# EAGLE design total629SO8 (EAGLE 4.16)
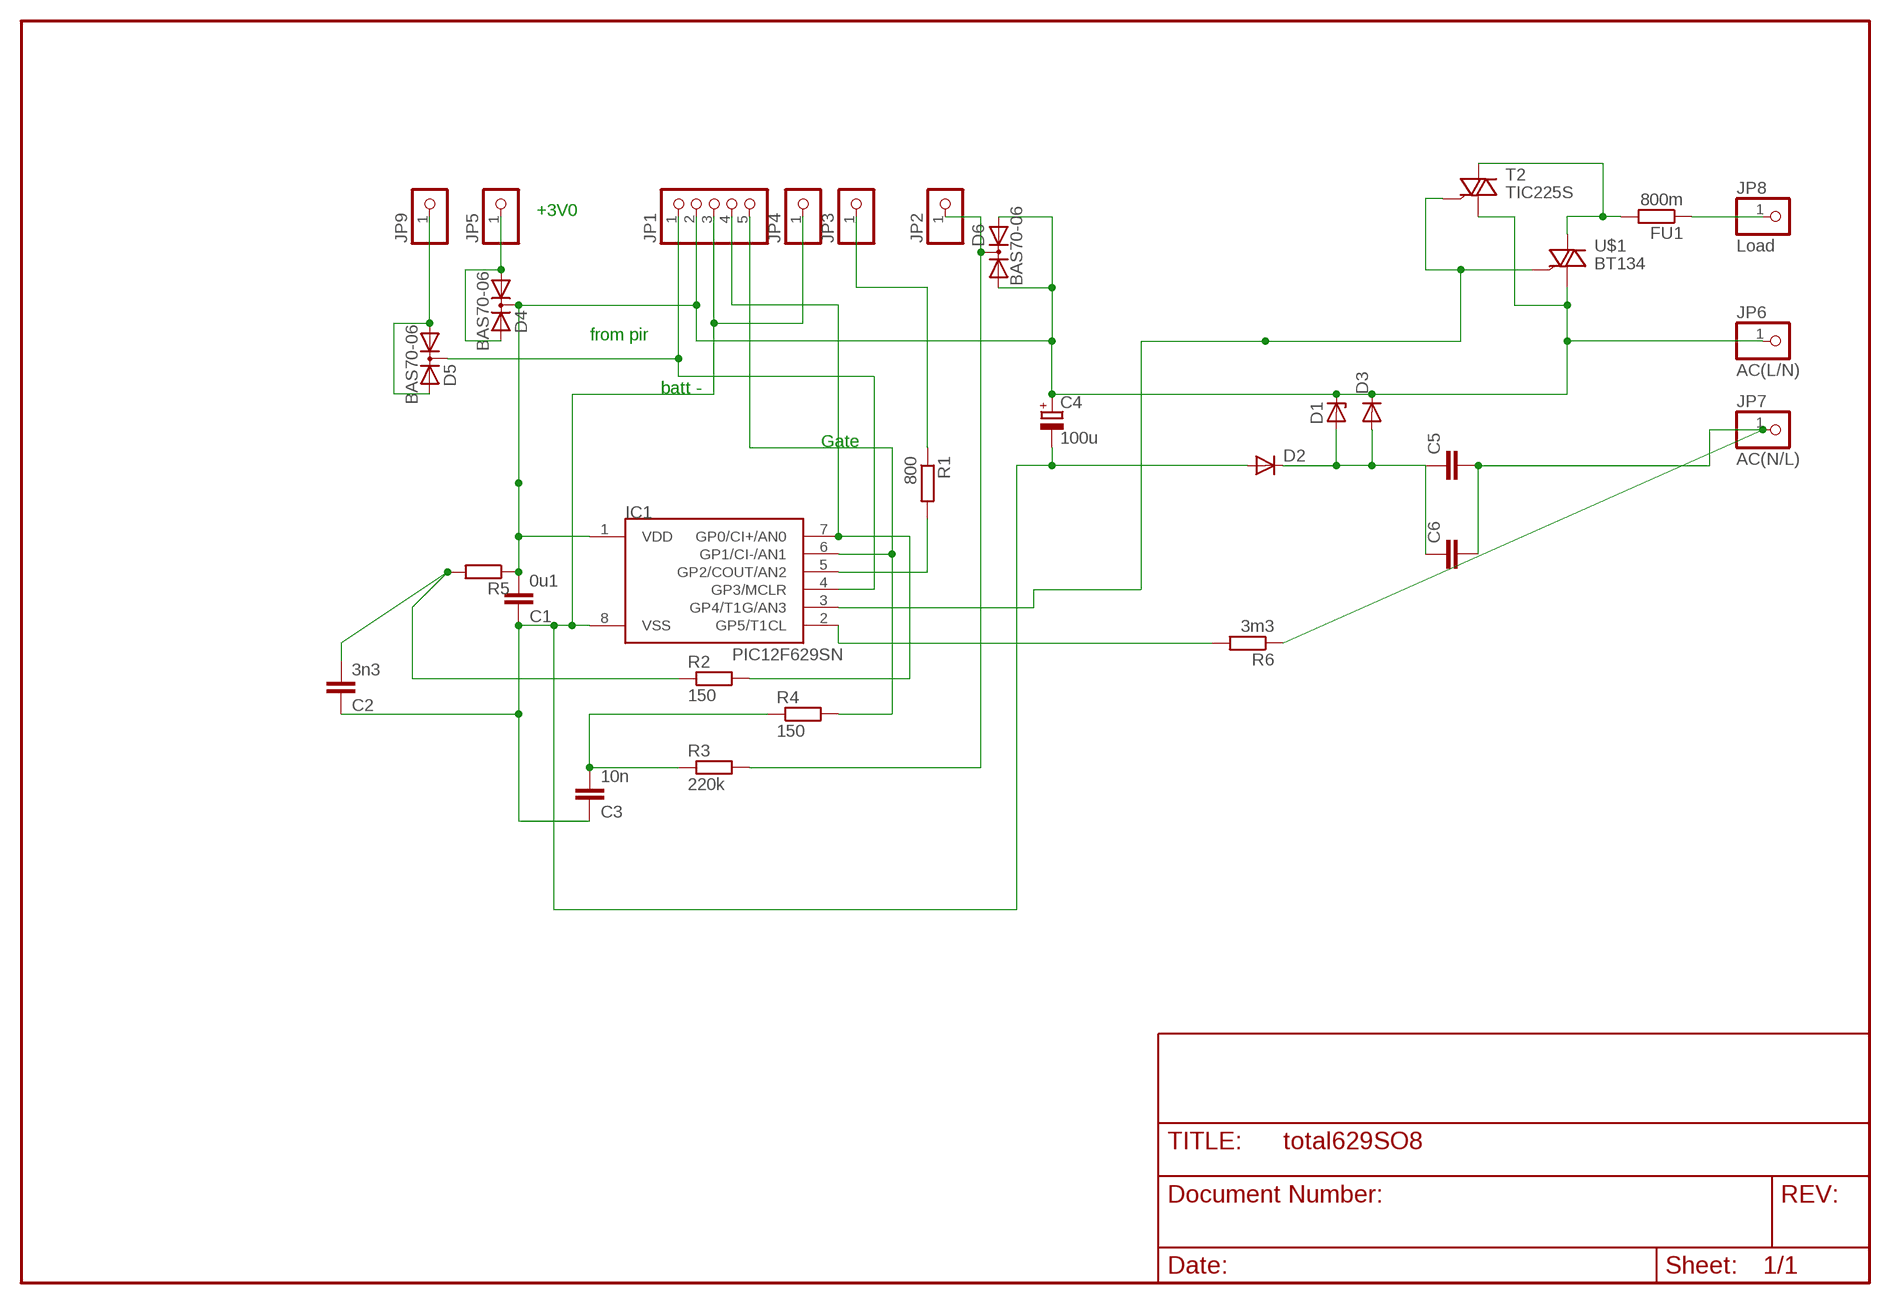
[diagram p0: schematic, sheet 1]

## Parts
C1  0u1  C-EUC1206  [C1206]
C2  3n3  C-EUC1206  [C1206]
C3  10n  C-EUC1206  [C1206]
C4  100u  CPOL-EUE2,5-6E  [E2,5-6E]
C5  C-EU075-032X103  [C075-032X103]
C6  C-EU102-043X133  [C102-043X133]
D1  ZENER-DIODEDO35Z10  [DO35Z10]
D2  DIODE-MELF-MLL41  [MELF-MLL41]
D3  DIODE-MINIMELF  [MINIMELF]
D4  BAS70-06  [SOT23]
D5  BAS70-06  [SOT23]
D6  BAS70-06  [SOT23]
FU1  800m  R-EU_0204/7  [0204/7]
IC1  PIC12F629SN  [SO-08]
JP1  PINHD-1X5  [1X05]
JP2  PINHD-1X1  [1X01]
JP3  PINHD-1X1  [1X01]
JP4  PINHD-1X1  [1X01]
JP5  PINHD-1X1  [1X01]
JP6  AC(L/N)  PINHD-1X1  [1X01]
JP7  AC(N/L)  PINHD-1X1  [1X01]
JP8  Load  PINHD-1X1  [1X01]
JP9  PINHD-1X1  [1X01]
R1  800  R-EU_M1206  [M1206]
R2  150  R-EU_M1206  [M1206]
R3  220k  R-EU_M1206  [M1206]
R4  150  R-EU_M1206  [M1206]
R5  R-EU_0613/5V  [P0613V]
R6  3m3  R-EU_R1206  [R1206]
T2  TIC225S  [TO220DS]
U$1  BT134  [SOT223]

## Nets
GATE: JP3.1 R1.1
N$1: IC1.5(GP2/COUT/AN2) R1.2
N$2: FU1.1 JP8.1
N$4: IC1.7(GP0/CI+/AN0) JP1.4 R2.2
N$6: C2.2 R2.1 R5.2
N$7: C3.2 R3.1 R4.1
N$8: IC1.6(GP1/CI-/AN1) JP1.5 R4.2
N$9: FU1.2 T2.A2 U$1.P$2(A2)
N$10: IC1.3(GP4/T1G/AN3) T2.G U$1.P$3(G)
N$12: C5.1 C6.1 D1.A D2.C D3.A
N$14: IC1.2(GP5/T1CL) R6.2
N$37: C5.2 C6.2 JP7.1 R6.1
PIR: D5.3(C) IC1.4(GP3/MCLR) JP1.1
SENSOR: D5.1(A1) D5.2(A2) JP9.1
V3: C1.2 C4.+ D1.C D3.C D4.3(C) D6.1(A1) D6.2(A2) IC1.1(VDD) JP1.2 JP6.1 R5.1 T2.A1 U$1.P$1(A1)
V+3: D6.3(C) JP2.1 R3.2
V+BATT: D4.1(A1) D4.2(A2) JP5.1
V-: C1.1 C2.1 C3.1 C4.- D2.A IC1.8(VSS) JP1.3 JP4.1

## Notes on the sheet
- +3V0
- from pir
- batt -
- Gate

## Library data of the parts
C1-C3 C5 = rcl:C-EU: CAPACITOR, European symbol
C4 = rcl(2):CPOL-EU: POLARIZED CAPACITOR, European symbol
C6 = rcl-2:C-EU: CAPACITOR, European symbol
D1 = diode-1:ZENER-DIODE: Z-Diode
D2 D3 = diode-1:DIODE-: DIODE
D4-D6 = diode-1:BAS70-06: Silicon Schottky Diodes General-purpose diode for high-speed switching
FU1 R1-R6 = rcl:R-EU_: RESISTOR, European symbol
IC1 = microchip-3:PIC12F6*: uPC nW 1k Program Flash memory 2x Timer Comparator 10b A/D converter/ 4xIN
JP1 = pinhead:PINHD-1X5: PIN HEADER
JP2-JP9 = pinhead:PINHD-1X1: PIN HEADER
T2 = triac:TIC225S: TRIAC
U$1 = triggered_devices:BT134

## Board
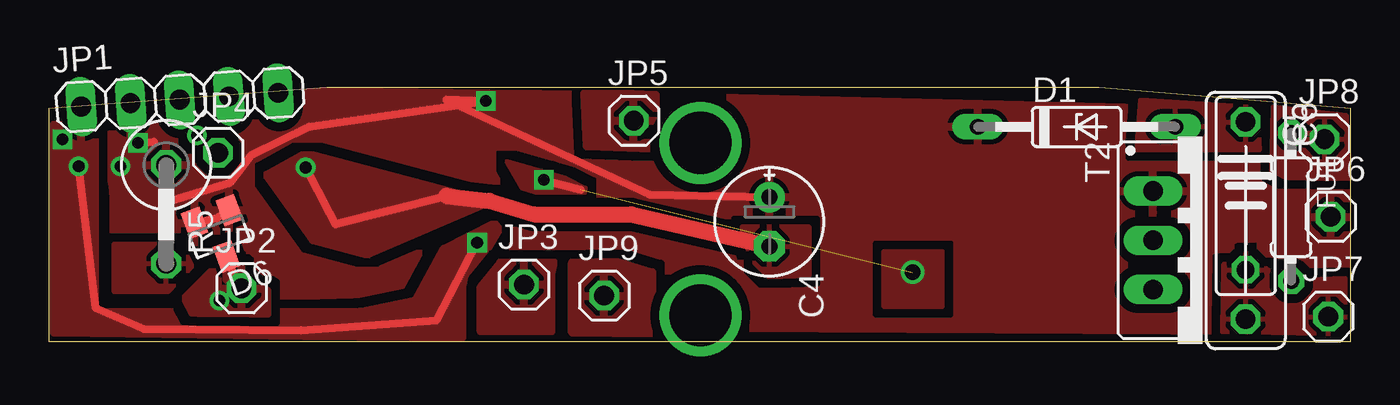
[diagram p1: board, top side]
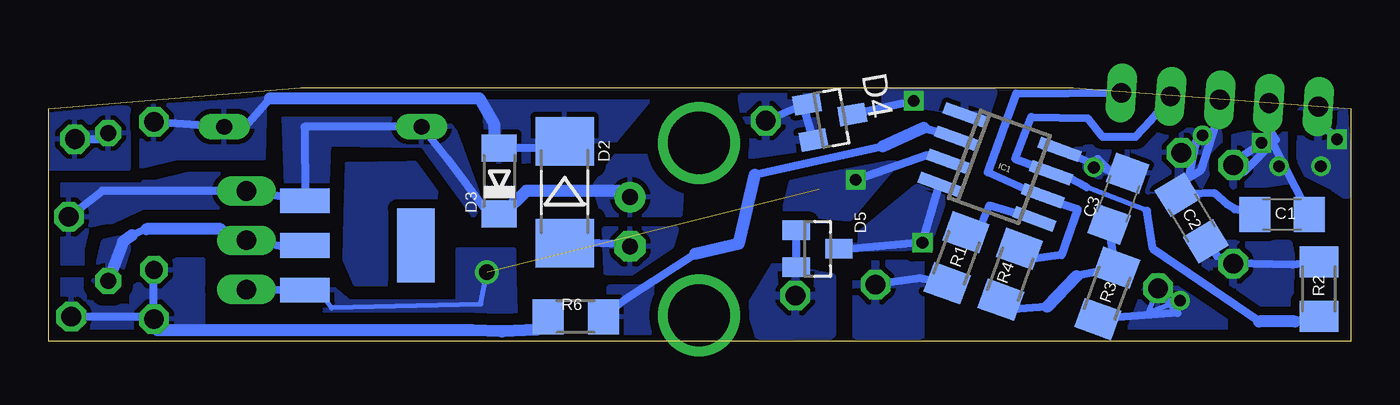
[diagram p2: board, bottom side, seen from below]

Size 67.04 x 13.08 mm. Coordinates in mm from the lower left corner, seen from the top.
Outline: 0,0 67.04,0 67.04,11.86 67.02,11.99 54.06,13.08 18,13.07 14.31,13.08 0,11.99 0,0
Copper layers (1*16): Top 0.035mm / dielectric 1.5mm / Bottom 0.035mm
Design rules "default": minimum track width 10mil, minimum drill 24mil, track to track 18mil, track to pad 18mil, pad to pad 8mil, via to via 8mil, smd to smd 8mil, copper to edge 1mil, drill to drill 8mil, minimum pad ring 10mil, minimum via ring 8mil, stop-mask expansion 4mil, vias tented up to drill 0mil, thermal gap 10mil

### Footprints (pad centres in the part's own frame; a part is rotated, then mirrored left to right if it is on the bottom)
C1206 = smd 1.6 x 1.8: 1 -1.4,0; 2 1.4,0
E2,5-6E = drill 0.813 pad 1.575 round: + -1.27,0 | drill 0.813 pad 1.575 octagon: - 1.27,0
C075-032X103 = drill 0.914 octagon: 1 -3.81,0; 2 3.81,0
C102-043X133 = drill 1.016 octagon: 1 -5.08,0; 2 5.08,0
DO35Z10 = drill 0.813 long: A 5.08,0; C -5.08,0
MELF-MLL41 = smd 2.5 x 3: A 2.625,0; C -2.625,0
MINIMELF = smd 1.4 x 1.8: A 1.7,0; C -1.7,0
SOT23 = smd 1 x 1.4: 1 -0.95,-1.1; 2 0.95,-1.1; 3 0,1.1
0204/7 = drill 0.813 octagon: 1 -3.81,0; 2 3.81,0
SO-08 = smd 0.6 x 2.2: 1 -1.905,-2.6; 2 -0.635,-2.6; 3 0.635,-2.6; 4 1.905,-2.6; 5 1.905,2.6; 6 0.635,2.6; 7 -0.635,2.6; 8 -1.905,2.6
1X05 = drill 1.016 long: 1 -5.08,0; 2 -2.54,0; 3 0,0; 4 2.54,0; 5 5.08,0
1X01 = drill 1.016 octagon: 1 0,0
M1206 = smd 1.6 x 2: 1 -1.4,0; 2 1.4,0
P0613V = drill 1.016 octagon: 1 -2.54,0; 2 2.54,0
R1206 = smd 1.6 x 1.803: 1 -1.422,0; 2 1.422,0
TO220DS = drill 1.016 long: A1 -2.54,-2.54; A2 0,-2.54; G 2.54,-2.54
SOT223 = smd 1.27 x 2.54: P$1 0.7,1.3; P$2 3,1.3; P$3 5.3,1.3 | smd 3.81 x 1.93: P$4 3,7

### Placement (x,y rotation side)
C1  3.55,6.53 0 bottom
C2  8.2,6.35 301.3 bottom
C3  11.98,7.34 250 bottom
C4  37.11,6.15 270 top
C5  61.62,7.49 270 top
C6  61.62,6.22 270 top
D1  52.92,11.04 0 top
D2  40.48,7.68 270 bottom
D3  43.84,8.25 90 bottom
D4  26.75,11.49 280 bottom
D5  27.46,4.76 270 bottom
D6  8.79,5.39 200 top
FU1  63.97,6.92 270 top
IC1  18.09,8.98 250 bottom
JP1  6.75,12.44 4 top
JP2  9.93,2.73 0 top
JP3  24.47,2.92 0 top
JP4  8.72,9.71 0 top
JP5  30.12,11.36 0 top
JP6  66,6.41 0 top
JP7  65.88,1.27 0 top
JP8  65.68,10.41 0 top
JP9  28.6,2.34 0 top
R1  20.31,4.3 70 bottom
R2  1.64,2.69 270 bottom
R3  12.55,2.46 250 bottom
R4  17.54,3.45 70 bottom
R5  6.06,6.54 270 top
R6  39.9,1.27 0 bottom
T2  59.4,5.2 270 top
U$1  55.14,7.93 270 bottom

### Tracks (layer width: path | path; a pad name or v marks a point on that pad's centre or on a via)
GATE
  Bottom 0.406: R1.1 22.2,3.24 JP3.1
  pour Bottom (rank 2): 22.31,4.38 25.49,4.38 25.49,0.31 22.12,0.31 22.12,4.19
  pour Top: 23.27,4.06 26,4.06 25.87,3.49 25.87,0.5 22.25,0.5 22.25,2.79
N$1
  Bottom 0.406: IC1.5 18.63,6.98 19.33,5.33 R1.2
N$2
  Bottom 0.406: FU1.1 64.03,10.73 64.35,10.41 JP8.1
  pour Top: 63.02,12.06 62.95,8.82 63.65,8.44 66.89,8.38 66.83,11.62
  pour Bottom: 62.95,12 62.95,8.88 67.02,8.88 67.02,11.68 63.34,12.06
N$4
  Bottom 0.254: 10.5,6.73 13.61,7.93
  Bottom 0.406: JP1.4 9.42,12.38 10.31,11.36 11.07,10.54 12.79,10.54 13.55,11.49 16.47,11.55 17.3,9.39 IC1.7 15.33,8.63 14.44,8.38 13.61,7.93 | 10.5,6.73 10.19,4.76 4.72,1.01 | R2.2 2.88,1.01
  Bottom 0.61: 2.88,1.01 4.72,1.01
N$6
  Bottom 0.406: R2.1 3.01,3.93 R5.2 6.88,4.38 C2.2
  pour Bottom: 3.2,5.01 7.14,5.01 8.15,4.25 4.79,1.96 3.14,1.96 3.07,4.38
  pour Top (isolate 0.61): 6.82,5.01 7.39,3.87 6.12,2.54 3.39,2.54 3.39,5.01
N$7
  Bottom 0.406: C3.2 12.15,3.87 R3.1 14.12,3.36 | R4.1 17.42,1.65 15.65,1.77
  Bottom 0.61: 14.12,3.36 15.65,1.77
N$8
  Bottom 0.406: JP1.5 17.23,12.76 18.69,8.69 16.47,7.68 15.96,7.42 | 15.96,7.42 IC1.6 | 15.96,7.42 14.06,6.79 14.88,4.44 16.73,4.19 R4.2
N$9
  Bottom 0.406: U$1.P$2 54.25,4.76 T2.A2 56.98,5.14 58.19,5.77 | 62,5.77 62.76,5.46
  Bottom 0.61: FU1.2 63.21,5.14 62.76,5.46 | 58.19,5.77 62,5.77
  pour Bottom: 63.4,5.33 64.22,5.14 64.73,3.11 63.59,2.6 62.89,4.82
N$10  (via drill 0.6, 0.8)  (1 unrouted)
  Top 0.406: v25.49,8.31 27.39,7.81
  Bottom 0.254: v44.48,3.55 44.79,1.9 52.48,1.71 53.18,2.66 53.68,2.66 U$1.P$3
  Bottom 0.406: IC1.3 21.81,9.58 v25.49,8.31 | T2.G 56.98,2.6 U$1.P$3
  pour Bottom: 23.52,9.14 25.87,6.34 29.11,6.66 28.73,8.19 23.77,9.14
  pour Bottom (isolate 0.61): 43.08,4.69 46,4.69 46,2.03 51.59,2.03 52.79,3.04 52.79,1.39 43.02,1.46 43.08,4.12
  pour Top: 43.02,4.63 46,4.63 46,1.77 43.02,1.77
  pour Top (isolate 0.61): 27.65,7.87 26.63,8.38 23.58,9.27 24.54,7.62 27.58,7.62
N$11  (via drill 3.2)
  other vias: 33.55,10.22
N$12
  Bottom 0.406: 55.65,12.5 56.92,11.04 D1.A 58.19,11.04 C6.1 | 44.09,10.15 43.89,9.95 D3.A 40.81,9.95 40.48,10.28 D2.C
  Bottom 0.61: 55.65,12.5 44.86,12.5 44.09,11.17 44.09,10.15
  pour Bottom: 57.05,12.38 62.26,12.06 62.26,9.01 60.41,9.46 55.97,9.46 55.91,12.5
  pour Top: 56.22,12.44 62.19,12.06 62.32,9.84 56.03,9.84
  pour Bottom (isolate 0.61, rank 3): 36.16,12.63 44.67,12.82 44.41,9.27 38.7,9.33 36.22,12.31
N$13  (via drill 3.2)
  other vias: 33.55,1.33
N$14
  Bottom 0.406: IC1.2 22,10.98 | 24.09,10.03 30.7,8.57 | R6.2 37.43,2.09 33.74,4.5
  Bottom 0.61: 22,10.98 24.09,10.03 | 30.7,8.57 31.52,5.01 33.74,4.5
  pour Bottom (isolate 0.305, rank 3): 35.97,3.11 36.09,0.38 38.19,0.38 38.19,2.79 36.66,3.11
N$37
  Bottom 0.406: JP7.1 61.56,1.27 61.62,1.2 C6.2 C5.2 | R6.1 41.9,0.59
  Bottom 0.61: C6.2 61.43,0.57 45.24,0.57 43.71,0.5 41.9,0.59
  pour Top: 60.48,3.93 60.41,0.5 66.76,0.38 66.76,3.23 63.53,3.11 61.68,4.5
  pour Bottom (isolate 0.61): 59.08,4.19 60.48,4.19 62.76,2.73 62.76,1.77 65.18,2.03 65.18,3.17 66.76,3.17 66.76,0.38 59.08,0.63
P$4
  pour Bottom (rank 2): 47.14,7.23 47.14,2.98 51.21,2.92 51.78,4.25 51.71,6.47 51.65,9.14 47.08,9.2
PIR  (via drill 0.6)
  Top 0.406: v0.72,10.41 0.91,10.41 0.98,10.35 | v1.55,9.01 2.44,1.71 4.91,0.63 12.98,0.57 19.96,1.07 v22.06,5.08
  Bottom 0.406: JP1.1 1.68,11.37 v0.72,10.41 | IC1.4 21.19,8.04 v22.06,5.08 26.25,4.69 D5.3
  pour Bottom: 20.92,6.98 21.36,4.95 25.87,4.88 22.31,7.81 20.79,7.17
  pour Bottom: 0.34,11.81 2.57,11.87 2.63,8.82 0.98,8 0.22,7.49 0.15,9.58
  pour Top (rank 2): 18.89,2.09 20.35,4.76 22.95,6.09 23.2,5.77 22.63,4.82 21.43,3.42 21.3,2.85 21.3,0.19 13.17,0.25 0.28,0.44 0.28,11.17 2.38,11.17 2.38,1.52 16.03,1.52
SENSOR
  Bottom 0.406: D5.2 28.54,3.81 28.54,5.71 D5.1
  pour Bottom: 26.7,0.38 26.7,3.3 29.68,3.87 30.95,1.77 30.51,0.31 26.89,0.25
  pour Top: 26.95,4.06 29.24,4.12 31.08,3.55 31.08,0.38 26.95,0.44
V3  (via drill 0.6)
  Top 0.406: v4.6,10.22 5.42,10.28 | D6.1 8.66,6.34 D6.2 | R5.1 6.06,7.17 9.36,8.19 10.44,9.58 13.42,11.04 v22.5,12.38 20.47,12.44 30.95,7.55 C4.+
  Bottom 0.406: 4.22,10.98 JP1.2 | 3.87,10.38 4.22,10.98 | 3.87,10.38 5.55,8.69 | 4.22,10.98 | 5.55,8.69 6.06,9.27 v4.6,10.22 | 3.87,10.38 4.28,10.73 C1.2 | 5.55,8.69 R5.1 6.06,8.95 | JP6.1 64.29,7.74 T2.A1 | T2.A1 56.79,7.74 | T2.A1 54.13,7.3 U$1.P$1 53.87,11.04 D1.C 46.51,9.39 44.48,6.66 43.9,6.66 43.84,6.6 D3.C 43.64,6.55 | C4.+ 37.24,7.42 37.3,7.36 37.68,7.74 | v22.5,12.38 D4.3
  Bottom 0.61: 43.64,6.55 42.44,7.74 37.68,7.74
  other vias: 3.71,9.01
  pour Bottom: 18.76,11.68 18.38,12.82 23.9,12.95 24.03,12.44
  pour Bottom (rank 2): 3.33,11.04 3.33,8.25 5.87,7.87 7.07,9.08 7.07,10.28
  pour Top (rank 3): 2.88,10.6 3.33,7.62 3.33,2.28 11.33,2.28 17.42,2.47 19.33,2.54 21.55,0.76 66.83,0.5 66.95,11.74 28.16,12.69 22.63,12.76 13.61,12.89
  pour Bottom (isolate 0.61, rank 2): 58.13,8.88 66.89,8.19 66.83,4 65.24,4 64.8,5.71 62.19,6.92 58.13,6.92
  pour Bottom (isolate 0.61): 48.48,11.68 54.95,11.62 54.83,8 52.67,8.19 52.6,10.15 47.78,10.09 45.17,6.47 44.79,7.23 46.13,10.79 46.7,11.62
  pour Bottom (isolate 0.61, rank 2): 38.51,6.54 34.51,6.54 34.44,7.74 36.09,9.52 37.87,9.52 38.95,8
V+3  (via drill 0.6)
  Top 0.406: JP2.1 9.93,2.54 D6.3
  Bottom 0.254: JP2.1 10.44,1.46 v8.79,2.09
  Bottom 0.406: JP2.1 8.92,1.46 R3.2
  pour Bottom (isolate 0.61, rank 2): 6.44,0.25 6.44,1.07 7.46,2.09 9.61,3.42 10.38,3.36 11.46,0.5 11.2,0.25
  pour Top: 9.8,3.87 11.26,2.6 11.26,1.39 7.46,1.39 7.01,2.22 9.11,4.31
V+BATT
  Bottom 0.406: D4.2 28.22,12.25 D4.1 30.06,11.36 JP5.1
  pour Bottom: 28.35,12.57 31.39,12.57 30.89,9.58 27.46,10.09 27.58,12.57
  pour Top: 31.27,12.69 31.14,9.9 27.71,10.03 27.58,12.76 30.06,12.76
V-  (via drill 0.6)
  Top 0.406: v13.23,8.95 14.76,6.03 20.47,7.49 | 37.17,4.88 C4.-
  Top 0.813: 20.47,7.49 22.69,7.23 24.98,6.54 30,6.54 37.17,4.88
  Bottom 0.406: IC1.8 11.39,8.31 C3.1 12.3,8.65 13.04,9.39 v13.23,8.95 | JP1.3 6.75,11.81 7.71,8.82 8.34,8.44 | 8.34,8.44 8.52,8.26 C2.1 7.02,7.63 6.38,7.04 5.98,6.8 C1.1 | 8.34,8.44 7.96,10.28 v7.65,10.6 | C4.- 36.79,5.01 D2.A
  pour Bottom (isolate 0.406): 6.76,10.79 6.76,9.96 7.2,9.52 7.2,8.95 7.77,7.81 10.44,7.68 11.14,7.93 13.49,8.57 14.12,9.9 9.87,10.85 9.17,10.85 9.04,10.92
  pour Top (isolate 0.61): 13.04,9.58 13.61,9.58 22.76,7.17 16.41,4.44 13.61,5.2 11.2,8.57
  pour Top: 35.71,5.9 39.14,5.9 39.14,3.36 37.11,3.3 36.22,4.19 35.71,5.58
  pour Bottom (isolate 0.61, rank 2): 34.7,5.77 38.44,5.77 38.38,3.55 37.05,3.49 34.95,4.88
